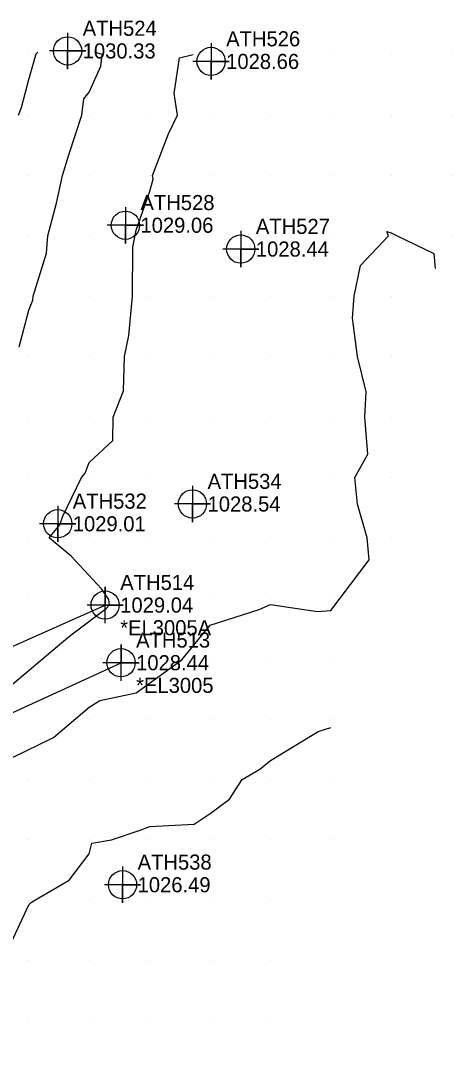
# Model space of a CAD drawing. Extents: x 1213164 to 1213550, y 766120 to 766870.
# Drawn here: x 1213478.6 to 1213550, y 766656 to 766825.7 of the extents above; entities that cross this region are included whole.
import ezdxf

# ---------------------------------------------------------------- set-up
doc = ezdxf.new("R2010")
doc.units = 0
for name, color, linetype in [('Default', 7, 'Continuous'), ('Exist DTM QL2 LIDAR Elevation Point', 7, 'Continuous'), ('Exist DTM Regular Point CELL', 7, 'Continuous'), ('Exist DTM Regular Point Cogo Elevation', 7, 'Continuous'), ('Exist DTM Regular Point Cogo Number', 7, 'Continuous'), ('Exist Roads Soil', 7, 'Continuous'), ('Exist Roads Soil Cogo Comment', 7, 'Continuous'), ('Exist Roads Soil Cogo Elevation', 7, 'Continuous'), ('Exist Roads Soil Cogo Number', 7, 'Continuous'), ('Exist Roads Soil Cogo Point CELL', 7, 'Continuous')]:
    doc.layers.add(name, color=color, linetype=linetype)

msp = doc.modelspace()

# ---------------------------------------------------------------- linework, layer by layer
at = {"layer": 'Default'}
for points in [[(1213478.24, 766810), (1213478.74, 766811.26), (1213480, 766815.88), (1213481.22, 766820.12), (1213481.48, 766820.43)], [(1213478.36, 766771.64), (1213480, 766777.71), (1213480.62, 766779.38), (1213480.7, 766780), (1213482.88, 766787.12), (1213483.1, 766790), (1213484.56, 766795.44), (1213485.56, 766800), (1213486.58, 766803.42), (1213488.74, 766810), (1213489.09, 766812.67), (1213490, 766813.81), (1213491.92, 766818.08), (1213492.13, 766820), (1213490.89, 766820.41)], [(1213464.83, 766705.35), (1213486.46, 766723.48), (1213487.45, 766724.3), (1213492.78, 766728.28), (1213493.36, 766728.92), (1213493.25, 766729.82), (1213491.99, 766731.55), (1213486.99, 766736.99), (1213483.37, 766740), (1213485.1, 766742.18), (1213485.62, 766743.59), (1213488.73, 766750), (1213489.3, 766750.7), (1213490, 766752.47), (1213493.88, 766756.12), (1213493.94, 766760), (1213495.66, 766764.34), (1213495.82, 766770), (1213496.52, 766773.48), (1213497.16, 766780), (1213497.22, 766788.13), (1213497.77, 766790.97), (1213500, 766797.39), (1213500.59, 766799.41), (1213500.49, 766800), (1213503.11, 766806.89), (1213504.61, 766810), (1213504.08, 766813.56), (1213504.94, 766819.46), (1213507.22, 766820)], [(1213470.22, 766700.19), (1213484.07, 766706.95), (1213489.96, 766711.98), (1213491.74, 766713.09), (1213497.78, 766714.35), (1213505.32, 766719.79), (1213510, 766725.53), (1213518.13, 766728.13), (1213520, 766728.96), (1213527.81, 766727.81), (1213530, 766727.96), (1213536.38, 766736.38), (1213536.03, 766740), (1213534.4, 766745.6), (1213534, 766750), (1213536.16, 766753.84), (1213535.63, 766760), (1213535.85, 766764.15), (1213534.45, 766770), (1213533.6, 766776.4), (1213533.86, 766780), (1213534.91, 766785.09), (1213539.55, 766790), (1213539.29, 766790.71), (1213540, 766790.5), (1213540.99, 766790), (1213547.08, 766787.08), (1213547.3, 766784.61)], [(1213464.06, 766655.94), (1213467.28, 766660), (1213469.12, 766660.88), (1213470, 766663.66), (1213473.54, 766666.46), (1213474.4, 766670), (1213477.04, 766672.96), (1213480, 766679.24), (1213480.39, 766679.61), (1213480.99, 766680), (1213486.65, 766683.35), (1213490, 766687.67), (1213490.42, 766689.43), (1213493.65, 766690), (1213498.42, 766691.58), (1213500, 766692.24), (1213507.38, 766692.62), (1213510, 766694.38), (1213513.24, 766696.76), (1213515.3, 766700), (1213518.27, 766701.73), (1213520, 766703.15), (1213527.93, 766707.93), (1213530, 766708.58)]]:
    msp.add_lwpolyline(points, dxfattribs=at)
at = {"layer": 'Exist DTM QL2 LIDAR Elevation Point'}
for p, q in [((1213480, 766820), (1213480, 766820)), ((1213490, 766820), (1213490, 766820)), ((1213500, 766820), (1213500, 766820)), ((1213520, 766820), (1213520, 766820)), ((1213530, 766820), (1213530, 766820)), ((1213540, 766820), (1213540, 766820)), ((1213550, 766820), (1213550, 766820)), ((1213480, 766810), (1213480, 766810)), ((1213490, 766810), (1213490, 766810)), ((1213500, 766810), (1213500, 766810)), ((1213510, 766810), (1213510, 766810)), ((1213520, 766810), (1213520, 766810)), ((1213530, 766810), (1213530, 766810)), ((1213540, 766810), (1213540, 766810)), ((1213550, 766810), (1213550, 766810)), ((1213480, 766800), (1213480, 766800)), ((1213490, 766800), (1213490, 766800)), ((1213500, 766800), (1213500, 766800)), ((1213510, 766800), (1213510, 766800)), ((1213520, 766800), (1213520, 766800)), ((1213530, 766800), (1213530, 766800)), ((1213540, 766800), (1213540, 766800)), ((1213550, 766800), (1213550, 766800)), ((1213480, 766790), (1213480, 766790)), ((1213490, 766790), (1213490, 766790)), ((1213500, 766790), (1213500, 766790)), ((1213510, 766790), (1213510, 766790)), ((1213520, 766790), (1213520, 766790)), ((1213530, 766790), (1213530, 766790)), ((1213540, 766790), (1213540, 766790)), ((1213550, 766790), (1213550, 766790)), ((1213480, 766780), (1213480, 766780)), ((1213490, 766780), (1213490, 766780)), ((1213500, 766780), (1213500, 766780)), ((1213510, 766780), (1213510, 766780)), ((1213520, 766780), (1213520, 766780)), ((1213530, 766780), (1213530, 766780)), ((1213540, 766780), (1213540, 766780)), ((1213480, 766770), (1213480, 766770)), ((1213490, 766770), (1213490, 766770)), ((1213500, 766770), (1213500, 766770)), ((1213510, 766770), (1213510, 766770)), ((1213520, 766770), (1213520, 766770)), ((1213530, 766770), (1213530, 766770)), ((1213540, 766770), (1213540, 766770)), ((1213480, 766760), (1213480, 766760)), ((1213490, 766760), (1213490, 766760)), ((1213500, 766760), (1213500, 766760)), ((1213510, 766760), (1213510, 766760)), ((1213520, 766760), (1213520, 766760)), ((1213530, 766760), (1213530, 766760)), ((1213540, 766760), (1213540, 766760)), ((1213480, 766750), (1213480, 766750)), ((1213490, 766750), (1213490, 766750)), ((1213500, 766750), (1213500, 766750)), ((1213510, 766750), (1213510, 766750)), ((1213520, 766750), (1213520, 766750)), ((1213530, 766750), (1213530, 766750)), ((1213540, 766750), (1213540, 766750)), ((1213480, 766740), (1213480, 766740)), ((1213490, 766740), (1213490, 766740)), ((1213500, 766740), (1213500, 766740)), ((1213510, 766740), (1213510, 766740)), ((1213520, 766740), (1213520, 766740)), ((1213530, 766740), (1213530, 766740)), ((1213540, 766740), (1213540, 766740)), ((1213480, 766730), (1213480, 766730)), ((1213510, 766730), (1213510, 766730)), ((1213520, 766730), (1213520, 766730)), ((1213530, 766730), (1213530, 766730)), ((1213510, 766720), (1213510, 766720)), ((1213520, 766720), (1213520, 766720)), ((1213530, 766720), (1213530, 766720)), ((1213490, 766710), (1213490, 766710)), ((1213500, 766710), (1213500, 766710)), ((1213510, 766710), (1213510, 766710)), ((1213520, 766710), (1213520, 766710)), ((1213530, 766710), (1213530, 766710)), ((1213480, 766700), (1213480, 766700)), ((1213490, 766700), (1213490, 766700)), ((1213500, 766700), (1213500, 766700)), ((1213510, 766700), (1213510, 766700)), ((1213520, 766700), (1213520, 766700)), ((1213530, 766700), (1213530, 766700)), ((1213480, 766690), (1213480, 766690)), ((1213490, 766690), (1213490, 766690)), ((1213500, 766690), (1213500, 766690)), ((1213510, 766690), (1213510, 766690)), ((1213520, 766690), (1213520, 766690)), ((1213530, 766690), (1213530, 766690)), ((1213480, 766680), (1213480, 766680)), ((1213490, 766680), (1213490, 766680)), ((1213500, 766680), (1213500, 766680)), ((1213510, 766680), (1213510, 766680)), ((1213520, 766680), (1213520, 766680)), ((1213480, 766670), (1213480, 766670)), ((1213490, 766670), (1213490, 766670)), ((1213500, 766670), (1213500, 766670)), ((1213510, 766670), (1213510, 766670)), ((1213520, 766670), (1213520, 766670)), ((1213480, 766660), (1213480, 766660)), ((1213490, 766660), (1213490, 766660)), ((1213500, 766660), (1213500, 766660)), ((1213510, 766660), (1213510, 766660)), ((1213520, 766660), (1213520, 766660))]:
    msp.add_line(p, q, dxfattribs=at)
at = {"layer": 'Exist DTM Regular Point CELL'}
for points in [[(1213486.4, 766823.62), (1213486.4, 766817.62), (1213486.4, 766820.62), (1213489.4, 766820.62), (1213483.4, 766820.62)], [(1213510.17, 766821.88), (1213510.17, 766815.88), (1213510.17, 766818.88), (1213513.17, 766818.88), (1213507.17, 766818.88)], [(1213495.97, 766794.76), (1213495.97, 766788.76), (1213495.97, 766791.76), (1213498.97, 766791.76), (1213492.97, 766791.76)], [(1213515.09, 766790.82), (1213515.09, 766784.82), (1213515.09, 766787.82), (1213518.09, 766787.82), (1213512.09, 766787.82)], [(1213507.09, 766748.61), (1213507.09, 766742.61), (1213507.09, 766745.61), (1213510.09, 766745.61), (1213504.09, 766745.61)], [(1213484.76, 766745.33), (1213484.76, 766739.33), (1213484.76, 766742.33), (1213487.76, 766742.33), (1213481.76, 766742.33)], [(1213495.5, 766685.57), (1213495.5, 766679.57), (1213495.5, 766682.57), (1213498.5, 766682.57), (1213492.5, 766682.57)]]:
    msp.add_lwpolyline(points, dxfattribs=at)
for centre in [(1213486.4, 766820.62), (1213510.17, 766818.88), (1213495.97, 766791.76), (1213515.09, 766787.82), (1213507.09, 766745.61), (1213484.76, 766742.33), (1213495.5, 766682.57)]:
    msp.add_circle(centre, 2.34, dxfattribs=at)
at = {"layer": 'Exist Roads Soil'}
for points in [[(1213390.96, 766664.77), (1213401.18, 766664.7), (1213428.51, 766689.46), (1213457.95, 766713.45), (1213492.62, 766728.87)], [(1213380.26, 766624.46), (1213403.81, 766652.91), (1213435.34, 766682.17), (1213462.6, 766704.33), (1213495.25, 766719.33)]]:
    msp.add_lwpolyline(points, dxfattribs=at)
at = {"layer": 'Exist Roads Soil Cogo Point CELL'}
for points in [[(1213492.62, 766725.87), (1213492.62, 766731.87), (1213492.62, 766728.87), (1213495.62, 766728.87), (1213489.62, 766728.87)], [(1213495.25, 766716.33), (1213495.25, 766722.33), (1213495.25, 766719.33), (1213498.25, 766719.33), (1213492.25, 766719.33)]]:
    msp.add_lwpolyline(points, dxfattribs=at)
for centre in [(1213492.62, 766728.87), (1213495.25, 766719.33)]:
    msp.add_circle(centre, 2.34, dxfattribs=at)

# ---------------------------------------------------------------- texts
at = {"layer": 'Exist DTM Regular Point Cogo Elevation'}
for s, p in [('1030.33', (1213488.9, 766819.37)), ('1028.66', (1213512.67, 766817.63)), ('1029.06', (1213498.47, 766790.51)), ('1028.44', (1213517.59, 766786.57)), ('1028.54', (1213509.59, 766744.36)), ('1029.01', (1213487.26, 766741.08)), ('1026.49', (1213498, 766681.32))]:
    msp.add_text(s, height=2.5, dxfattribs=at).set_placement(p)
at = {"layer": 'Exist DTM Regular Point Cogo Number'}
for s, p in [('ATH524', (1213488.9, 766823.12)), ('ATH526', (1213512.67, 766821.38)), ('ATH528', (1213498.47, 766794.26)), ('ATH527', (1213517.59, 766790.32)), ('ATH534', (1213509.59, 766748.11)), ('ATH532', (1213487.26, 766744.83)), ('ATH538', (1213498, 766685.07))]:
    msp.add_text(s, height=2.5, dxfattribs=at).set_placement(p)
at = {"layer": 'Exist Roads Soil Cogo Comment'}
for s, p in [('*EL3005A', (1213495.12, 766723.87)), ('*EL3005', (1213497.75, 766714.33))]:
    msp.add_text(s, height=2.5, dxfattribs=at).set_placement(p)
at = {"layer": 'Exist Roads Soil Cogo Elevation'}
for s, p in [('1029.04', (1213495.12, 766727.62)), ('1028.44', (1213497.75, 766718.08))]:
    msp.add_text(s, height=2.5, dxfattribs=at).set_placement(p)
at = {"layer": 'Exist Roads Soil Cogo Number'}
for s, p in [('ATH514', (1213495.12, 766731.37)), ('ATH513', (1213497.75, 766721.83))]:
    msp.add_text(s, height=2.5, dxfattribs=at).set_placement(p)

doc.saveas('drawing.dxf')
